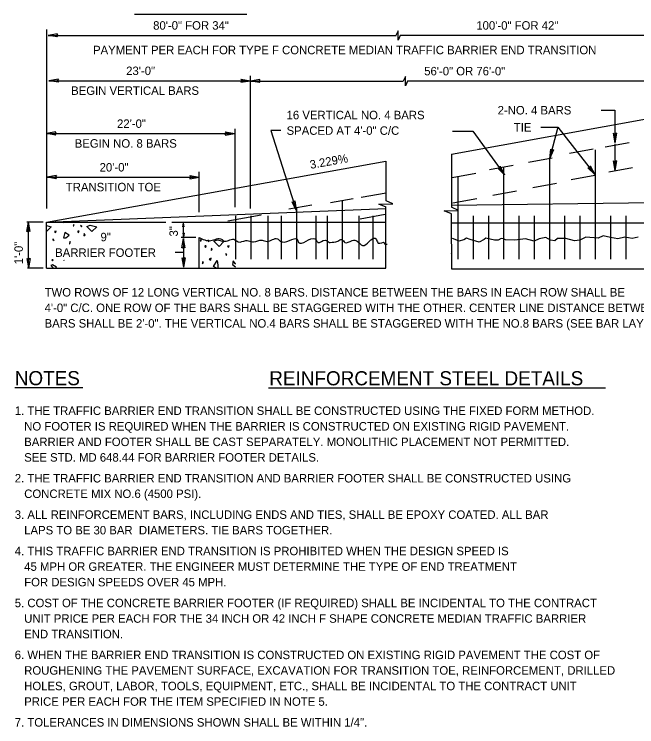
# Model space of a CAD drawing. Extents: x -0.8 to 6.5, y 10.6 to 20.8.
# Drawn here: x -0.78 to 3.63, y 12.06 to 17.1 of the extents above; entities that cross this region are included whole.
import ezdxf

# ---------------------------------------------------------------- set-up
doc = ezdxf.new("R2010")
doc.units = 0
for name, color, linetype in [('DETL-DIMS', 7, 'Continuous'), ('DETL-LINE', 7, 'Continuous'), ('DETL-NOTE', 7, 'Continuous'), ('DETL-PATT', 7, 'Continuous'), ('DETL-TITL', 7, 'Continuous')]:
    doc.layers.add(name, color=color, linetype=linetype)

msp = doc.modelspace()

# ---------------------------------------------------------------- linework, layer by layer
at = {"layer": 'DETL-DIMS'}
for p, q in [((-0.5486, 15.7293), (-0.5486, 16.9945)), ((1.937, 16.9865), (1.9217, 16.9543)), ((1.9377, 16.9205), (1.937, 16.9865)), ((-0.4728, 16.9653), (-0.5399, 16.9541)), ((-0.5399, 16.9541), (1.922, 16.9541)), ((-0.4728, 16.9428), (-0.5399, 16.9541)), ((-0.4728, 16.9653), (-0.4813, 16.9541)), ((-0.4728, 16.9428), (-0.4813, 16.9541)), ((1.9524, 16.9543), (1.9377, 16.9205)), ((4.0784, 16.9541), (1.9522, 16.9541)), ((-0.4669, 16.6447), (-0.5342, 16.6334)), ((-0.5342, 16.6334), (0.8922, 16.6334)), ((-0.4669, 16.6222), (-0.5342, 16.6334)), ((-0.4669, 16.6447), (-0.4754, 16.6334)), ((-0.4669, 16.6222), (-0.4754, 16.6334)), ((0.8249, 16.6447), (0.8922, 16.6334)), ((0.8249, 16.6447), (0.8334, 16.6334)), ((0.8249, 16.6222), (0.8922, 16.6334)), ((0.8249, 16.6222), (0.8334, 16.6334)), ((0.8922, 15.7293), (0.8922, 16.6675)), ((0.9593, 16.6425), (0.8922, 16.6314)), ((0.8922, 16.6314), (1.9737, 16.6314)), ((0.9593, 16.6202), (0.8922, 16.6314)), ((0.9593, 16.6425), (0.951, 16.6314)), ((0.9593, 16.6202), (0.951, 16.6314)), ((1.9882, 16.6634), (1.9729, 16.6312)), ((1.9887, 16.5974), (1.9882, 16.6634)), ((2.0035, 16.6312), (1.9887, 16.5974)), ((3.9782, 16.6314), (2.0037, 16.6314)), ((3.3725, 16.4247), (3.4708, 16.4247)), ((3.4708, 16.4247), (3.4708, 16.1949)), ((0.7837, 15.7403), (0.7837, 16.2938)), ((1.0353, 16.2808), (1.2156, 15.7175)), ((1.1078, 16.2808), (1.0353, 16.2808)), ((2.3216, 16.2768), (2.4651, 16.2768)), ((2.4651, 16.2768), (2.6904, 15.9681)), ((2.9472, 16.3039), (3.0672, 16.3039)), ((3.0672, 16.3039), (3.0082, 16.0818)), ((3.0672, 16.3039), (3.3295, 15.9706)), ((-0.4846, 16.2711), (-0.5519, 16.2598)), ((-0.5519, 16.2598), (0.7804, 16.2598)), ((-0.4846, 16.2486), (-0.5519, 16.2598)), ((-0.4846, 16.2711), (-0.4931, 16.2598)), ((-0.4846, 16.2486), (-0.4931, 16.2598)), ((0.7132, 16.2711), (0.7804, 16.2598)), ((0.7132, 16.2711), (0.7217, 16.2598)), ((0.7132, 16.2486), (0.7804, 16.2598)), ((0.7132, 16.2486), (0.7217, 16.2598)), ((3.4596, 16.2621), (3.4708, 16.1949)), ((3.4596, 16.2621), (3.4708, 16.2538)), ((3.4819, 16.2621), (3.4708, 16.1949)), ((3.4819, 16.2621), (3.4708, 16.2538)), ((3.4708, 16.1879), (3.4708, 15.9988)), ((3.0147, 16.1496), (3.0082, 16.0818)), ((3.0362, 16.1438), (3.0082, 16.0818)), ((3.0147, 16.1496), (3.0234, 16.1386)), ((3.0362, 16.1438), (3.0234, 16.1386)), ((2.6599, 16.029), (2.6557, 16.0156)), ((2.6599, 16.029), (2.6904, 15.9681)), ((3.2968, 16.0303), (3.2931, 16.0168)), ((3.2968, 16.0303), (3.3295, 15.9706)), ((3.4596, 16.066), (3.4708, 15.9988)), ((3.4596, 16.066), (3.4708, 16.0576)), ((3.4819, 16.066), (3.4708, 15.9988)), ((3.4819, 16.066), (3.4708, 16.0576)), ((0.5291, 15.704), (0.5291, 15.9893)), ((2.6417, 16.0158), (2.6904, 15.9681)), ((2.6417, 16.0158), (2.6557, 16.0156)), ((3.2791, 16.0165), (3.2931, 16.0168)), ((3.2791, 16.0165), (3.3295, 15.9706)), ((-0.4804, 15.9625), (-0.5477, 15.9513)), ((-0.5477, 15.9513), (0.5301, 15.9513)), ((-0.4804, 15.94), (-0.5477, 15.9513)), ((-0.4804, 15.9625), (-0.4889, 15.9513)), ((-0.4804, 15.94), (-0.4889, 15.9513)), ((0.4629, 15.9625), (0.5301, 15.9513)), ((0.4629, 15.9625), (0.4713, 15.9513)), ((0.4629, 15.94), (0.5301, 15.9513)), ((0.4629, 15.94), (0.4713, 15.9513)), ((1.1845, 15.778), (1.2156, 15.7175)), ((1.1845, 15.778), (1.1978, 15.7735)), ((1.2058, 15.7848), (1.1978, 15.7735)), ((1.2058, 15.7848), (1.2156, 15.7175)), ((-0.5737, 15.6332), (-0.6907, 15.6332)), ((-0.6896, 15.5664), (-0.6784, 15.6335)), ((-0.6784, 15.3097), (-0.6784, 15.6335)), ((-0.6672, 15.5664), (-0.6784, 15.6335)), ((0.4138, 15.5995), (0.4186, 15.6284)), ((0.4186, 15.5275), (0.4186, 15.6284)), ((0.4234, 15.5995), (0.4186, 15.6284)), ((-0.6896, 15.5664), (-0.6784, 15.5747)), ((-0.6672, 15.5664), (-0.6784, 15.5747)), ((0.4138, 15.5995), (0.4186, 15.603)), ((0.4234, 15.5995), (0.4186, 15.603)), ((0.5063, 15.5242), (0.4029, 15.5242)), ((0.4138, 15.5562), (0.4186, 15.5275)), ((0.4138, 15.5562), (0.4186, 15.5527)), ((0.4234, 15.5562), (0.4186, 15.5275)), ((0.4234, 15.5562), (0.4186, 15.5527)), ((0.4074, 15.4507), (0.4186, 15.5179)), ((0.4186, 15.5179), (0.4186, 15.3139)), ((0.4298, 15.4507), (0.4186, 15.5179)), ((0.4074, 15.4507), (0.4186, 15.4591)), ((0.4298, 15.4507), (0.4186, 15.4591)), ((-0.6896, 15.3771), (-0.6784, 15.3097)), ((-0.6896, 15.3771), (-0.6784, 15.3686)), ((-0.6672, 15.3771), (-0.6784, 15.3097)), ((-0.6672, 15.3771), (-0.6784, 15.3686)), ((0.4186, 15.4179), (0.3589, 15.4179)), ((0.4074, 15.3812), (0.4186, 15.3139)), ((0.4074, 15.3812), (0.4186, 15.3727)), ((0.4298, 15.3812), (0.4186, 15.3139)), ((0.4298, 15.3812), (0.4186, 15.3727)), ((-0.5737, 15.3082), (-0.6861, 15.3082))]:
    msp.add_line(p, q, dxfattribs=at)
at = {"layer": 'DETL-LINE'}
for p, q in [((2.3148, 16.1141), (4.0967, 16.4381)), ((3.4025, 16.1668), (3.5706, 16.1973)), ((3.1502, 16.1201), (3.3181, 16.1506)), ((3.3315, 16.1441), (3.3315, 15.3711)), ((2.3148, 16.1141), (2.3148, 15.738)), ((2.8587, 16.0585), (3.0269, 16.089)), ((3.0074, 16.0855), (3.0074, 15.3711)), ((-0.5519, 15.6327), (1.851, 16.0646)), ((1.851, 16.0646), (1.851, 15.785)), ((2.5826, 16.0065), (2.7507, 16.037)), ((2.6834, 16.0246), (2.6834, 15.3711)), ((2.3196, 15.9483), (2.4876, 15.979)), ((3.4275, 15.9895), (3.5954, 16.02)), ((2.3595, 15.9556), (2.3595, 15.3711)), ((3.1605, 15.9338), (3.3285, 15.9643)), ((2.8902, 15.8778), (3.0582, 15.9085)), ((1.6756, 15.8098), (1.8515, 15.8415)), ((2.6059, 15.8243), (2.7741, 15.8548)), ((1.4574, 15.7725), (1.6192, 15.8015)), ((1.5419, 15.7877), (1.5419, 15.3711)), ((1.9005, 15.7617), (1.8514, 15.785)), ((2.314, 15.7522), (4.4203, 15.7817)), ((2.325, 15.7695), (2.4931, 15.8)), ((-0.5519, 15.6327), (1.8535, 15.7307)), ((1.1648, 15.7265), (1.3271, 15.7557)), ((1.218, 15.736), (1.218, 15.3711)), ((1.7999, 15.7608), (1.9005, 15.7617)), ((1.8514, 15.7383), (1.7999, 15.7608)), ((1.851, 15.3086), (1.851, 15.7392)), ((2.3643, 15.7148), (2.3151, 15.7382)), ((0.7322, 15.6429), (0.968, 15.6852)), ((0.7859, 15.6785), (0.7859, 15.3711)), ((0.8939, 15.6785), (0.8939, 15.3711)), ((1.0147, 15.6785), (1.0147, 15.3711)), ((1.11, 15.6785), (1.11, 15.3711)), ((1.3546, 15.6785), (1.3546, 15.3711)), ((1.4339, 15.6785), (1.4339, 15.3711)), ((1.6596, 15.6785), (1.6596, 15.3711)), ((1.6682, 15.6575), (1.8442, 15.6892)), ((1.7579, 15.6785), (1.7579, 15.3711)), ((2.2636, 15.714), (2.3643, 15.7148)), ((2.3151, 15.6915), (2.2636, 15.714)), ((2.3148, 15.4787), (2.3148, 15.6923)), ((2.4674, 15.6785), (2.4674, 15.3711)), ((2.5754, 15.6785), (2.5754, 15.3711)), ((2.7914, 15.6785), (2.7914, 15.3711)), ((2.8994, 15.6785), (2.8994, 15.3711)), ((3.1153, 15.6785), (3.1153, 15.3711)), ((3.2235, 15.6785), (3.2235, 15.3711)), ((3.4395, 15.6785), (3.4395, 15.3711)), ((3.5474, 15.6785), (3.5474, 15.3711)), ((-0.5519, 15.3086), (-0.5519, 15.6327)), ((-0.5519, 15.6327), (0.2933, 15.6327)), ((0.3356, 15.6327), (1.8514, 15.6327)), ((2.3148, 15.6282), (4.4203, 15.6282)), ((0.5281, 15.3086), (0.5281, 15.5247)), ((2.3148, 15.478), (2.3148, 15.3037)), ((2.3148, 15.4099), (2.3148, 15.4106)), ((-0.5519, 15.3086), (0.5281, 15.3086)), ((0.5281, 15.3086), (1.851, 15.3086)), ((2.3148, 15.3037), (4.4203, 15.3037))]:
    msp.add_line(p, q, dxfattribs=at)
msp.add_lwpolyline([(3.6353, 15.5275), (3.5931, 15.5177), (3.5411, 15.5275), (3.4924, 15.5145), (3.4406, 15.5242), (3.3886, 15.5372), (3.353, 15.521), (3.2653, 15.5275), (3.2232, 15.5047), (3.1843, 15.5015), (3.1225, 15.5177), (3.0642, 15.5177), (3.0447, 15.5015), (3.0155, 15.5047), (2.983, 15.5242), (2.9344, 15.5145), (2.8987, 15.4984), (2.8371, 15.5145), (2.7626, 15.5047), (2.6976, 15.508), (2.6814, 15.5145), (2.6651, 15.5177), (2.6456, 15.5047), (2.6198, 15.5047), (2.5581, 15.521), (2.5451, 15.5112), (2.5094, 15.4919), (2.4478, 15.5112), (2.4218, 15.521), (2.4023, 15.508), (2.3666, 15.4984), (2.3635, 15.5015), (2.3213, 15.5177)], dxfattribs=at)
msp.add_spline([(0.5281, 15.5247), (0.6112, 15.503), (0.6877, 15.5125), (0.7036, 15.4999), (0.7737, 15.5125), (0.8055, 15.4934), (0.8597, 15.503), (0.898, 15.4967), (0.9139, 15.4934), (0.9745, 15.5062), (1.0095, 15.4967), (1.0828, 15.5157), (1.102, 15.4999), (1.1688, 15.503), (1.223, 15.5125), (1.2326, 15.4902), (1.3473, 15.5157), (1.3633, 15.4967), (1.3696, 15.4902), (1.4206, 15.5062), (1.4524, 15.4902), (1.4556, 15.4902), (1.5098, 15.4999), (1.5386, 15.5094), (1.5608, 15.4902), (1.6117, 15.503), (1.6469, 15.4999), (1.6851, 15.4679), (1.7744, 15.5189), (1.7902, 15.4934), (1.7967, 15.4839), (1.838, 15.487), (1.838, 15.4839), (1.8475, 15.4775), (1.8604, 15.4775)], degree=3, dxfattribs=at)
at = {"layer": 'DETL-NOTE'}
msp.add_line((-0.7757, 14.4632), (-0.2933, 14.4632), dxfattribs=at)
at = {"layer": 'DETL-PATT'}
for points in [[(-0.4336, 15.6327), (-0.4313, 15.6285), (-0.4303, 15.6327)], [(-0.5519, 15.6094), (-0.5181, 15.6007), (-0.5519, 15.5669)], [(-0.4854, 15.3086), (-0.4798, 15.3156), (-0.5081, 15.3319), (-0.5206, 15.3261), (-0.5043, 15.3086)], [(-0.4286, 15.3634), (-0.4254, 15.3621), (-0.4258, 15.3634)], [(0.6524, 15.3086), (0.6297, 15.3184), (0.6562, 15.3631), (0.6601, 15.3284), (0.6617, 15.3086)], [(0.7859, 15.3372), (0.7854, 15.3386), (0.769, 15.3587), (0.7652, 15.3327), (0.7859, 15.3179)]]:
    msp.add_lwpolyline(points, dxfattribs=at)
for points in [[(-0.4941, 15.568), (-0.4841, 15.5599), (-0.4821, 15.5699)], [(-0.3568, 15.6165), (-0.3626, 15.6064), (-0.3568, 15.6064)], [(-0.3304, 15.5699), (-0.3266, 15.5579), (-0.3203, 15.5699)], [(-0.304, 15.6007), (-0.3001, 15.6025), (-0.3103, 15.6107)], [(-0.2416, 15.6127), (-0.1951, 15.6007), (-0.2296, 15.566), (-0.2661, 15.6025)], [(-0.4154, 15.5215), (-0.3909, 15.542), (-0.4211, 15.5599), (-0.4313, 15.5215)], [(-0.2838, 15.5522), (-0.2863, 15.5359), (-0.2781, 15.544)], [(-0.5061, 15.5157), (-0.5061, 15.5095), (-0.4979, 15.5037)], [(-0.3889, 15.4792), (-0.3871, 15.4792), (-0.3833, 15.4955)], [(0.5429, 15.5124), (0.5372, 15.5022), (0.5429, 15.5022)], [(0.5957, 15.4965), (0.5996, 15.4984), (0.5896, 15.5065)], [(0.6581, 15.5085), (0.7047, 15.4965), (0.6701, 15.4619), (0.6337, 15.4984)], [(0.5694, 15.4657), (0.5732, 15.4537), (0.5794, 15.4657)], [(0.6159, 15.4481), (0.6136, 15.4317), (0.6217, 15.4399)], [(0.7287, 15.4639), (0.7387, 15.4557), (0.7407, 15.4657)], [(0.5996, 15.3712), (0.6116, 15.3649), (0.6136, 15.3794)], [(0.7167, 15.4116), (0.7167, 15.4052), (0.7249, 15.3996)], [(-0.5143, 15.3664), (-0.5081, 15.3602), (-0.5043, 15.3664)], [(0.5531, 15.3529), (0.5531, 15.3386), (0.5592, 15.3467)]]:
    msp.add_lwpolyline(points, close=True, dxfattribs=at)
at = {"layer": 'DETL-TITL'}
for p, q in [((0.0715, 17.1035), (0.8672, 17.1035)), ((1.0188, 14.4607), (3.4045, 14.4607))]:
    msp.add_line(p, q, dxfattribs=at)

# ---------------------------------------------------------------- texts
at = {"layer": 'DETL-NOTE'}
for s, height, p in [('80\'-0" FOR 34"', 0.059991, (0.2035, 16.9943)), ('100\'-0" FOR 42"', 0.059991, (2.4902, 16.9943)), ('PAYMENT PER EACH FOR TYPE F CONCRETE MEDIAN TRAFFIC BARRIER END TRANSITION', 0.06, (-0.2218, 16.8205)), ('23\'-0"', 0.06, (0.0126, 16.6734)), ('56\'-0" OR 76\'-0"', 0.059991, (2.1214, 16.6713)), ('BEGIN VERTICAL BARS', 0.06, (-0.3768, 16.5334)), ('2-NO. 4 BARS', 0.06, (2.641, 16.3947)), ('16 VERTICAL NO. 4 BARS', 0.06, (1.1477, 16.3607)), ('22\'-0"', 0.06, (-0.052, 16.2998)), ('TIE', 0.06, (2.7556, 16.2739)), ('SPACED AT 4\'-0" C/C', 0.06, (1.1477, 16.2508)), ('BEGIN NO. 8 BARS', 0.06, (-0.3514, 16.1598)), ('20\'-0"', 0.06, (-0.1751, 15.9912)), ('TRANSITION TOE', 0.06, (-0.4145, 15.8512)), ('9" ', 0.06, (-0.1689, 15.4979)), ('BARRIER FOOTER', 0.06, (-0.4898, 15.3879)), ('TWO ROWS OF 12 LONG VERTICAL NO. 8 BARS. DISTANCE BETWEEN THE BARS IN EACH ROW SHALL BE', 0.06, (-0.5645, 15.1074)), ('4\'-0" C/C. ONE ROW OF THE BARS SHALL BE STAGGERED WITH THE OTHER. CENTER LINE DISTANCE BETWEEN THE', 0.06, (-0.5645, 14.9974)), ('BARS SHALL BE 2\'-0". THE VERTICAL NO.4 BARS SHALL BE STAGGERED WITH THE NO.8 BARS (SEE BAR LAYOUT)', 0.06, (-0.5645, 14.8873)), ('NOTES', 0.1, (-0.7756, 14.4802)), ('1. THE TRAFFIC BARRIER END TRANSITION SHALL BE CONSTRUCTED USING THE FIXED FORM METHOD.', 0.06, (-0.7756, 14.2696)), ('   NO FOOTER IS REQUIRED WHEN THE BARRIER IS CONSTRUCTED ON EXISTING RIGID PAVEMENT.', 0.06, (-0.7756, 14.1596)), ('   BARRIER AND FOOTER SHALL BE CAST SEPARATELY. MONOLITHIC PLACEMENT NOT PERMITTED.', 0.06, (-0.7756, 14.0496)), ('   SEE STD. MD 648.44 FOR BARRIER FOOTER DETAILS.', 0.06, (-0.7756, 13.9396)), ('2. THE TRAFFIC BARRIER END TRANSITION AND BARRIER FOOTER SHALL BE CONSTRUCTED USING', 0.06, (-0.7756, 13.7922)), ('   CONCRETE MIX NO.6 (4500 PSI).', 0.06, (-0.7756, 13.6823)), ('3. ALL REINFORCEMENT BARS, INCLUDING ENDS AND TIES, SHALL BE EPOXY COATED. ALL BAR', 0.06, (-0.7757, 13.5349)), ('   LAPS TO BE 30 BAR  DIAMETERS. TIE BARS TOGETHER.', 0.06, (-0.7757, 13.4249)), ('4. THIS TRAFFIC BARRIER END TRANSITION IS PROHIBITED WHEN THE DESIGN SPEED IS', 0.06, (-0.7757, 13.2776)), ('   45 MPH OR GREATER. THE ENGINEER MUST DETERMINE THE TYPE OF END TREATMENT', 0.06, (-0.7757, 13.1675)), ('   FOR DESIGN SPEEDS OVER 45 MPH.', 0.06, (-0.7757, 13.0575)), ('5. COST OF THE CONCRETE BARRIER FOOTER (IF REQUIRED) SHALL BE INCIDENTAL TO THE CONTRACT', 0.06, (-0.7757, 12.9102)), ('   UNIT PRICE PER EACH FOR THE 34 INCH OR 42 INCH F SHAPE CONCRETE MEDIAN TRAFFIC BARRIER', 0.06, (-0.7757, 12.8002)), ('   END TRANSITION.', 0.06, (-0.7757, 12.6902)), ('6. WHEN THE BARRIER END TRANSITION IS CONSTRUCTED ON EXISTING RIGID PAVEMENT THE COST OF ', 0.06, (-0.7757, 12.5429)), ('   ROUGHENING THE PAVEMENT SURFACE, EXCAVATION FOR TRANSITION TOE, REINFORCEMENT, DRILLED ', 0.06, (-0.7757, 12.4329)), ('   HOLES, GROUT, LABOR, TOOLS, EQUIPMENT, ETC., SHALL BE INCIDENTAL TO THE CONTRACT UNIT', 0.06, (-0.7757, 12.323)), ('   PRICE PER EACH FOR THE ITEM SPECIFIED IN NOTE 5.', 0.06, (-0.7757, 12.213)), ('7. TOLERANCES IN DIMENSIONS SHOWN SHALL BE WITHIN 1/4".', 0.06, (-0.7757, 12.0656))]:
    msp.add_text(s, height=height, dxfattribs=at).set_placement(p)
for s, height, rotation, p in [('3.229%', 0.05999, 10.1917, (1.318, 16.0094)), ('3"', 0.06, 90, (0.3785, 15.5315)), ('1\'-0"', 0.06, 90, (-0.7184, 15.3353))]:
    msp.add_text(s, height=height, rotation=rotation, dxfattribs=at).set_placement(p)
at = {"layer": 'DETL-TITL'}
msp.add_text('REINFORCEMENT STEEL DETAILS', height=0.1, dxfattribs=at).set_placement((1.0253, 14.4793))

doc.saveas('drawing.dxf')
